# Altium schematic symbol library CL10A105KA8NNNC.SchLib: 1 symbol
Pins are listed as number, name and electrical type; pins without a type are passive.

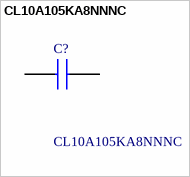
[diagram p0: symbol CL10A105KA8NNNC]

## CL10A105KA8NNNC
designator C?
Samsung Electro-Mechanics 0603 CL 1uF Ceramic Multilayer Capacitor, 25 V, +85C, X5R Dielectric, +/-10% SMD; Geometry.Height: 0.9mm
footprint CAPC1608X90N
pins: 1, 2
